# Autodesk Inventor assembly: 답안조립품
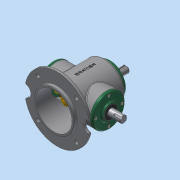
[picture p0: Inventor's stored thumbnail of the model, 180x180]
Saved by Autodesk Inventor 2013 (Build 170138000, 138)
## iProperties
Created: 2018-04
Part Number: 답안조립품
Document SubType Name: Assembly
Designer: dgall
Author: dgall
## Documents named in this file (16)
- C:\Users\dgall\Desktop\480407V1019\답안조립품.iam
- C:\Users\dgall\Desktop\480407V1019\본체.ipt
- C:\Users\dgall\Desktop\480407V1019\커버.ipt
- C:\Users\dgall\Desktop\480407V1019\베어링 6203.ipt
- C:\Users\dgall\Desktop\480407V1019\오일 실.ipt
- 오일 실.ipt
- C:\Users\dgall\Desktop\480407V1019\메인 축.ipt
- 메인 축.ipt
- C:\Users\dgall\Desktop\480407V1019\키 5x5.ipt
- C:\Users\dgall\Desktop\480407V1019\메인 베벨기어.ipt
- C:\Users\dgall\Desktop\480407V1019\볼트 M4.ipt
- 볼트 M4.ipt
- C:\Users\dgall\Desktop\480407V1019\서브 축.ipt
- 서브 축.ipt
- C:\Users\dgall\Desktop\480407V1019\키 4x4.ipt
- C:\Users\dgall\Desktop\480407V1019\서브 베벨기어.ipt
